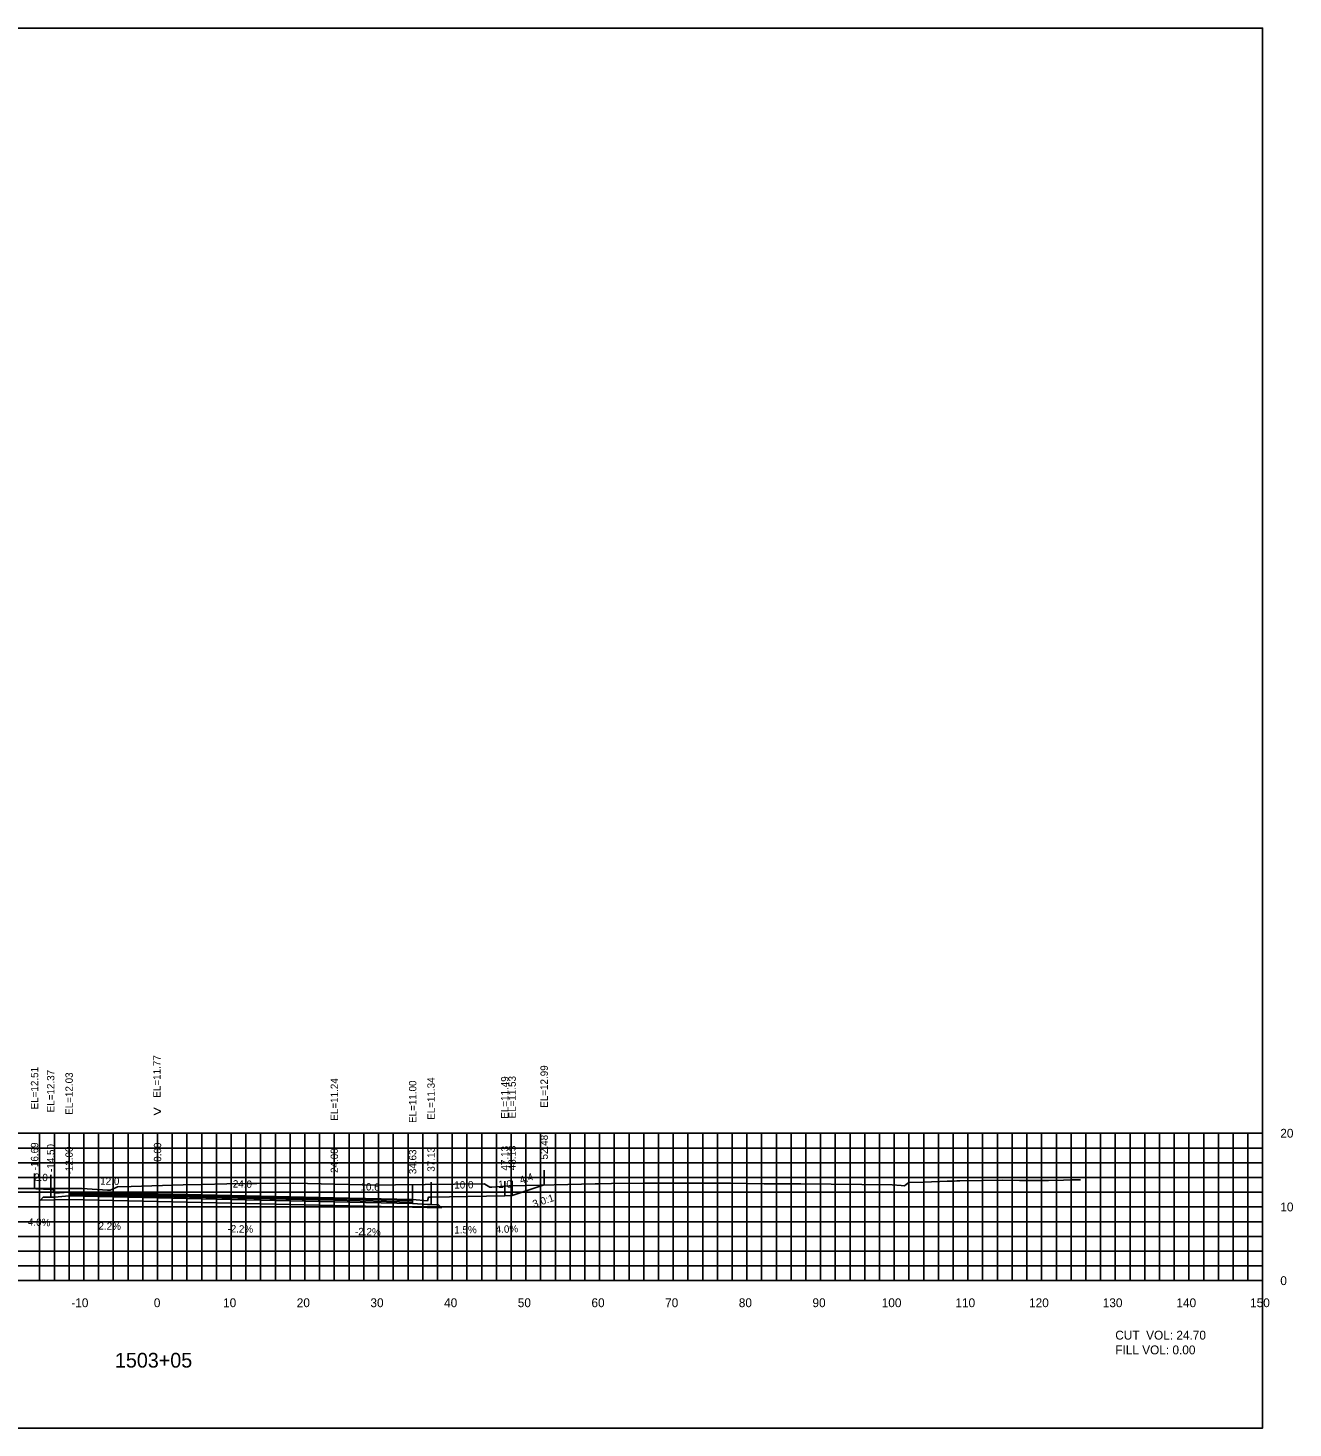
# Model space of a CAD drawing. Extents: x 1800674 to 1802785, y 250079 to 250269.
# Drawn here: x 1802613.4 to 1802785.1, y 250079.4 to 250269.4 of the extents above; entities that cross this region are included whole.
import ezdxf

# ---------------------------------------------------------------- set-up
doc = ezdxf.new("R2010")
doc.units = 0
for name, color, linetype in [('1', 7, 'Continuous'), ('10', 7, 'Continuous'), ('3', 7, 'Continuous'), ('31', 7, 'Continuous'), ('4', 7, 'Continuous'), ('60', 7, 'Continuous'), ('ANNO-TXT', 7, 'Continuous'), ('BASE', 7, 'Continuous'), ('CL-CNST', 7, 'Continuous'), ('Level 62', 7, 'Continuous'), ('LOWER BINDER', 7, 'Continuous'), ('M-ROADS', 7, 'Continuous'), ('UPPER BINDER', 7, 'Continuous'), ('WEARING', 7, 'Continuous')]:
    doc.layers.add(name, color=color, linetype=linetype)

msp = doc.modelspace()

# ---------------------------------------------------------------- linework, layer by layer
for p, q in [((1802683.48, 250112.42), (1802683.48, 250114.42)), ((1802614.31, 250111.95), (1802614.31, 250113.95)), ((1802616.5, 250111.8), (1802616.5, 250113.8)), ((1802619, 250111.46), (1802619, 250113.46)), ((1802631, 250111.2), (1802631, 250113.2)), ((1802655, 250110.67), (1802655, 250112.67)), ((1802665.63, 250110.44), (1802665.63, 250112.44)), ((1802668.13, 250110.78), (1802668.13, 250112.78)), ((1802678.13, 250110.93), (1802678.13, 250112.93)), ((1802679.13, 250110.97), (1802679.13, 250112.97))]:
    msp.add_line(p, q)
for points in [[(1802481, 250079.43), (1802781, 250079.43), (1802781, 250269.43), (1802481, 250269.43)], [(1802619, 250111.46), (1802617, 250111.3), (1802616.83, 250111.8), (1802616.5, 250111.8), (1802616.5, 250110.77), (1802617, 250110.77), (1802619, 250110.93)], [(1802665.63, 250110.44), (1802667.63, 250110.28), (1802667.8, 250110.78), (1802668.13, 250110.78), (1802668.13, 250109.75), (1802667.63, 250109.75), (1802665.63, 250109.91)]]:
    msp.add_lwpolyline(points, close=True)
at = {"layer": '60'}
for p, q in [((1802781, 250099.43), (1802781, 250119.43)), ((1802781.06, 250119.43), (1802781, 250119.43)), ((1802781.06, 250109.43), (1802781, 250109.43)), ((1802481, 250099.43), (1802781, 250099.43)), ((1802621, 250099.37), (1802621, 250099.43)), ((1802631, 250099.37), (1802631, 250099.43)), ((1802641, 250099.37), (1802641, 250099.43)), ((1802651, 250099.37), (1802651, 250099.43)), ((1802661, 250099.37), (1802661, 250099.43)), ((1802671, 250099.37), (1802671, 250099.43)), ((1802681, 250099.37), (1802681, 250099.43)), ((1802691, 250099.37), (1802691, 250099.43)), ((1802701, 250099.37), (1802701, 250099.43)), ((1802711, 250099.37), (1802711, 250099.43)), ((1802721, 250099.37), (1802721, 250099.43)), ((1802731, 250099.37), (1802731, 250099.43)), ((1802741, 250099.37), (1802741, 250099.43)), ((1802751, 250099.37), (1802751, 250099.43)), ((1802761, 250099.37), (1802761, 250099.43)), ((1802771, 250099.37), (1802771, 250099.43)), ((1802781, 250099.37), (1802781, 250099.43)), ((1802781.06, 250099.43), (1802781, 250099.43))]:
    msp.add_line(p, q, dxfattribs=at)
at = {"layer": 'BASE'}
msp.add_lwpolyline([(1802665.63, 250109.41), (1802669.53, 250109.32), (1802669.13, 250109.72), (1802668.13, 250109.75), (1802667.63, 250109.75), (1802665.63, 250109.91), (1802655, 250110.14), (1802631, 250110.67), (1802619, 250110.93), (1802617, 250110.77), (1802616.5, 250110.77), (1802615.5, 250110.75), (1802615.1, 250110.35), (1802619, 250110.43), (1802631, 250110.17), (1802655, 250109.64)], close=True, dxfattribs=at)
at = {"layer": 'CL-CNST'}
msp.add_lwpolyline([(1802614.31, 250111.95), (1802614.5, 250111.88), (1802616.5, 250111.8), (1802616.83, 250111.8), (1802617, 250111.3), (1802619, 250111.46), (1802631, 250111.2), (1802655, 250110.67), (1802665.63, 250110.44), (1802667.63, 250110.28), (1802667.8, 250110.78), (1802668.13, 250110.78), (1802678.13, 250110.93), (1802679.13, 250110.97), (1802683.48, 250112.42)], dxfattribs=at)
at = {"layer": 'Level 62'}
for p, q in [((1802481, 250119.43), (1802781, 250119.43)), ((1802615, 250099.43), (1802615, 250119.43)), ((1802617, 250099.43), (1802617, 250119.43)), ((1802619, 250099.43), (1802619, 250119.43)), ((1802621, 250099.43), (1802621, 250119.43)), ((1802623, 250099.43), (1802623, 250119.43)), ((1802625, 250099.43), (1802625, 250119.43)), ((1802627, 250099.43), (1802627, 250119.43)), ((1802629, 250099.43), (1802629, 250119.43)), ((1802631, 250099.43), (1802631, 250119.43)), ((1802633, 250099.43), (1802633, 250119.43)), ((1802635, 250099.43), (1802635, 250119.43)), ((1802637, 250099.43), (1802637, 250119.43)), ((1802639, 250099.43), (1802639, 250119.43)), ((1802641, 250099.43), (1802641, 250119.43)), ((1802643, 250099.43), (1802643, 250119.43)), ((1802645, 250099.43), (1802645, 250119.43)), ((1802647, 250099.43), (1802647, 250119.43)), ((1802649, 250099.43), (1802649, 250119.43)), ((1802651, 250099.43), (1802651, 250119.43)), ((1802653, 250099.43), (1802653, 250119.43)), ((1802655, 250099.43), (1802655, 250119.43)), ((1802657, 250099.43), (1802657, 250119.43)), ((1802659, 250099.43), (1802659, 250119.43)), ((1802661, 250099.43), (1802661, 250119.43)), ((1802663, 250099.43), (1802663, 250119.43)), ((1802665, 250099.43), (1802665, 250119.43)), ((1802667, 250099.43), (1802667, 250119.43)), ((1802669, 250099.43), (1802669, 250119.43)), ((1802671, 250099.43), (1802671, 250119.43)), ((1802673, 250099.43), (1802673, 250119.43)), ((1802675, 250099.43), (1802675, 250119.43)), ((1802677, 250099.43), (1802677, 250119.43)), ((1802679, 250099.43), (1802679, 250119.43)), ((1802681, 250099.43), (1802681, 250119.43)), ((1802683, 250099.43), (1802683, 250119.43)), ((1802685, 250099.43), (1802685, 250119.43)), ((1802687, 250099.43), (1802687, 250119.43)), ((1802689, 250099.43), (1802689, 250119.43)), ((1802691, 250099.43), (1802691, 250119.43)), ((1802693, 250099.43), (1802693, 250119.43)), ((1802695, 250099.43), (1802695, 250119.43)), ((1802697, 250099.43), (1802697, 250119.43)), ((1802699, 250099.43), (1802699, 250119.43)), ((1802701, 250099.43), (1802701, 250119.43)), ((1802703, 250099.43), (1802703, 250119.43)), ((1802705, 250099.43), (1802705, 250119.43)), ((1802707, 250099.43), (1802707, 250119.43)), ((1802709, 250099.43), (1802709, 250119.43)), ((1802711, 250099.43), (1802711, 250119.43)), ((1802713, 250099.43), (1802713, 250119.43)), ((1802715, 250099.43), (1802715, 250119.43)), ((1802717, 250099.43), (1802717, 250119.43)), ((1802719, 250099.43), (1802719, 250119.43)), ((1802721, 250099.43), (1802721, 250119.43)), ((1802723, 250099.43), (1802723, 250119.43)), ((1802725, 250099.43), (1802725, 250119.43)), ((1802727, 250099.43), (1802727, 250119.43)), ((1802729, 250099.43), (1802729, 250119.43)), ((1802731, 250099.43), (1802731, 250119.43)), ((1802733, 250099.43), (1802733, 250119.43)), ((1802735, 250099.43), (1802735, 250119.43)), ((1802737, 250099.43), (1802737, 250119.43)), ((1802739, 250099.43), (1802739, 250119.43)), ((1802741, 250099.43), (1802741, 250119.43)), ((1802743, 250099.43), (1802743, 250119.43)), ((1802745, 250099.43), (1802745, 250119.43)), ((1802747, 250099.43), (1802747, 250119.43)), ((1802749, 250099.43), (1802749, 250119.43)), ((1802751, 250099.43), (1802751, 250119.43)), ((1802753, 250099.43), (1802753, 250119.43)), ((1802755, 250099.43), (1802755, 250119.43)), ((1802757, 250099.43), (1802757, 250119.43)), ((1802759, 250099.43), (1802759, 250119.43)), ((1802761, 250099.43), (1802761, 250119.43)), ((1802763, 250099.43), (1802763, 250119.43)), ((1802765, 250099.43), (1802765, 250119.43)), ((1802767, 250099.43), (1802767, 250119.43)), ((1802769, 250099.43), (1802769, 250119.43)), ((1802771, 250099.43), (1802771, 250119.43)), ((1802773, 250099.43), (1802773, 250119.43)), ((1802775, 250099.43), (1802775, 250119.43)), ((1802777, 250099.43), (1802777, 250119.43)), ((1802779, 250099.43), (1802779, 250119.43)), ((1802781, 250099.43), (1802781, 250119.43)), ((1802481, 250117.43), (1802781, 250117.43)), ((1802481, 250115.43), (1802781, 250115.43)), ((1802481, 250113.43), (1802781, 250113.43)), ((1802481, 250111.43), (1802781, 250111.43)), ((1802481, 250109.43), (1802781, 250109.43)), ((1802481, 250107.43), (1802781, 250107.43)), ((1802481, 250105.43), (1802781, 250105.43)), ((1802481, 250103.43), (1802781, 250103.43)), ((1802481, 250101.43), (1802781, 250101.43)), ((1802481, 250099.43), (1802781, 250099.43))]:
    msp.add_line(p, q, dxfattribs=at)
at = {"layer": 'LOWER BINDER'}
msp.add_lwpolyline([(1802619, 250110.93), (1802619, 250111.12), (1802631, 250110.86), (1802655, 250110.33), (1802665.63, 250110.1), (1802665.63, 250109.91), (1802655, 250110.14), (1802631, 250110.67)], close=True, dxfattribs=at)
at = {"layer": 'M-ROADS'}
msp.add_lwpolyline([(1802608.28, 250111.95), (1802615.38, 250111.95), (1802618.54, 250111.94), (1802620.78, 250111.94), (1802622.13, 250111.85), (1802624.19, 250111.72), (1802624.36, 250111.7), (1802624.59, 250111.69), (1802624.81, 250111.8), (1802625.58, 250112.17), (1802627.42, 250112.22), (1802634.48, 250112.42), (1802637.11, 250112.49), (1802640.41, 250112.56), (1802643.19, 250112.61), (1802644.46, 250112.62), (1802649.49, 250112.67), (1802660.62, 250112.41), (1802663.31, 250112.42), (1802675.33, 250112.57), (1802675.43, 250112.51), (1802676.11, 250112.12), (1802676.37, 250112.13), (1802678.71, 250112.3), (1802679.24, 250112.32), (1802690.41, 250112.59), (1802691.09, 250112.59), (1802692.6, 250112.61), (1802697.09, 250112.65), (1802697.87, 250112.66), (1802708.32, 250112.66), (1802708.83, 250112.66), (1802713.33, 250112.59), (1802718.31, 250112.55), (1802730.72, 250112.44), (1802731.94, 250112.33), (1802732.37, 250112.28), (1802732.6, 250112.47), (1802732.96, 250112.74), (1802734.94, 250112.8), (1802737.19, 250112.88), (1802738.16, 250112.91), (1802739.12, 250112.92), (1802739.5, 250112.96), (1802739.73, 250112.97), (1802739.9, 250112.97), (1802743.08, 250113.04), (1802745.69, 250113.05), (1802747.99, 250113.03), (1802749.39, 250113.02), (1802750.28, 250113.02), (1802751.95, 250113.03), (1802753.95, 250113.07), (1802754.91, 250113.09), (1802756.3, 250113.1)], dxfattribs=at)
at = {"layer": 'UPPER BINDER'}
msp.add_lwpolyline([(1802631, 250110.86), (1802619, 250111.12), (1802619, 250111.31), (1802631, 250111.05), (1802655, 250110.52), (1802665.63, 250110.29), (1802665.63, 250109.91), (1802665.63, 250110.1), (1802655, 250110.33)], close=True, dxfattribs=at)
at = {"layer": 'WEARING'}
msp.add_lwpolyline([(1802665.63, 250110.29), (1802665.63, 250110.44), (1802655, 250110.67), (1802631, 250111.2), (1802619, 250111.46), (1802619, 250111.31), (1802631, 250111.05), (1802655, 250110.52)], close=True, dxfattribs=at)

# ---------------------------------------------------------------- texts
msp.add_text('3.0:1', height=1, rotation=18.4349).set_placement((1802682.1, 250109.32))
at = {"layer": '1'}
msp.add_text('1503+05', height=2, dxfattribs=at).set_placement((1802625.22, 250087.63))
at = {"layer": '10'}
for s, p in [('-10', (1802619.3, 250095.83)), ('0', (1802630.5, 250095.83)), ('10', (1802639.9, 250095.83)), ('20', (1802649.9, 250095.83)), ('30', (1802659.9, 250095.83)), ('40', (1802669.9, 250095.83)), ('50', (1802679.9, 250095.83)), ('60', (1802689.9, 250095.83)), ('70', (1802699.9, 250095.83)), ('80', (1802709.9, 250095.83)), ('90', (1802719.9, 250095.83)), ('100', (1802729.3, 250095.83)), ('110', (1802739.3, 250095.83)), ('120', (1802749.3, 250095.83)), ('130', (1802759.3, 250095.83)), ('140', (1802769.3, 250095.83)), ('150', (1802779.3, 250095.83))]:
    msp.add_text(s, height=1.2, dxfattribs=at).set_placement(p)
at = {"layer": '3'}
for s, p in [('EL=11.77', (1802631.42, 250124.26)), ('EL=12.51', (1802614.81, 250122.67)), ('EL=12.37', (1802617, 250122.27)), ('EL=12.03', (1802619.5, 250121.93)), ('EL=12.99', (1802683.98, 250122.89)), ('EL=11.24', (1802655.5, 250121.14)), ('EL=11.00', (1802666.13, 250120.83)), ('EL=11.34', (1802668.63, 250121.25)), ('EL=11.49', (1802678.63, 250121.4)), ('EL=11.53', (1802679.63, 250121.44)), ('-16.69', (1802614.81, 250114.4)), ('-14.50', (1802617, 250114.18)), ('0.00', (1802631.5, 250115.56)), ('52.48', (1802683.98, 250115.87)), ('-12.00', (1802619.5, 250113.84)), ('24.00', (1802655.5, 250114.04)), ('34.63', (1802666.13, 250113.88)), ('37.13', (1802668.63, 250114.22)), ('47.13', (1802678.63, 250114.37)), ('48.13', (1802679.63, 250114.41))]:
    msp.add_text(s, height=1, rotation=90, dxfattribs=at).set_placement(p)
at = {"layer": '31'}
for s, p in [('20', (1802783.4, 250118.83)), ('10', (1802783.4, 250108.83)), ('0', (1802783.4, 250098.83))]:
    msp.add_text(s, height=1.2, dxfattribs=at).set_placement(p)
at = {"layer": '4'}
for s, rotation, p in [('2.0', 357.7094, (1802614.23, 250112.99)), ('12.0', 358.7397, (1802623.21, 250112.47)), ('24.0', 358.7397, (1802641.21, 250112.07)), ('10.6', 358.7397, (1802658.54, 250111.69)), ('10.0', 0.8594, (1802671.29, 250111.92)), ('1.0', 2.2906, (1802677.26, 250111.99)), ('4.4', 18.4349, (1802680.34, 250112.55)), ('4.0%', 357.7094, (1802613.39, 250106.92)), ('2.2%', 358.7397, (1802622.98, 250106.37)), ('-2.2%', 358.7397, (1802640.48, 250105.99)), ('-2.2%', 358.7397, (1802657.8, 250105.61)), ('1.5%', 0.8594, (1802671.29, 250105.82)), ('4.0%', 2.2906, (1802676.92, 250105.87))]:
    msp.add_text(s, height=1, rotation=rotation, dxfattribs=at).set_placement(p)
at = {"layer": '60'}
msp.add_text('>', height=1.5, dxfattribs=at).set_placement((1802630.39, 250121.68))
at = {"layer": 'ANNO-TXT'}
for s, p in [('CUT  VOL: 24.70', (1802761, 250091.43)), ('FILL VOL: 0.00', (1802761, 250089.43))]:
    msp.add_text(s, height=1.2, dxfattribs=at).set_placement(p)

doc.saveas('drawing.dxf')
